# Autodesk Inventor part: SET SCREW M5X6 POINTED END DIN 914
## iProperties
IsCustomPart: 1
Created: 2006-02
Part Number: SET SCREW M5X6 POINTED END DIN 914
Material: Steel, Mild
Description: Hexagon Socket Set Screw
Document SubType Name: Modeling
Standard: DIN 914
Designer: Andy Moles
Standards Organization: DIN
Language: en-US
Size Designation: M5 x 6
Categories: <MemberInstance><Categories><Category DisplayName="Fasteners" InternalName="e4da775c-781d-43d5-af7c-5136215cf5a6" Mnemonic="FSTN"><Category DisplayName="Bolts"
Density: 1 g/cm^3
Author: Andy Moles
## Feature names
1. Body [Revolution]
2. Slot [Extrusion]
3. Chamfer1
4. Chamfer2
